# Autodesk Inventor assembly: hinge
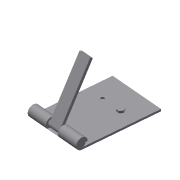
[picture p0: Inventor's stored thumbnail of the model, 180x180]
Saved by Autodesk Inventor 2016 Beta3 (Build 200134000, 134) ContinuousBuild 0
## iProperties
Created: 2016-03
Part Number: hinge
Document SubType Name: Assembly
Designer: Gaurav
Author: Gaurav
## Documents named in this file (4)
- D:\My Data\Books_Final Books\Autodesk Inventor 2015_resources\Chapter 7\Hinge\hinge.iam
- D:\My Data\Books_Final Books\Autodesk Inventor 2015_resources\Chapter 7\Hinge\base.ipt
- D:\My Data\Books_Final Books\Autodesk Inventor 2015_resources\Chapter 7\Hinge\movable_plate.ipt
- D:\My Data\Books_Final Books\Autodesk Inventor 2015_resources\Chapter 7\Hinge\bolt.ipt
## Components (3 placed, 3 different names)
1. base:1 — Mate:1, Rigid:1, Rotational:1
2. bolt:1 — Rigid:1
3. movable_plate:1 — Rotational:1
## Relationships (3: Mate 1, WeldJoint 1, RevoluteJoint 1)
- Mate:1: base:1
- Rigid:1 [WeldJoint]: base:1 ↔ bolt:1
- Rotational:1 [RevoluteJoint]: base:1 ↔ movable_plate:1
